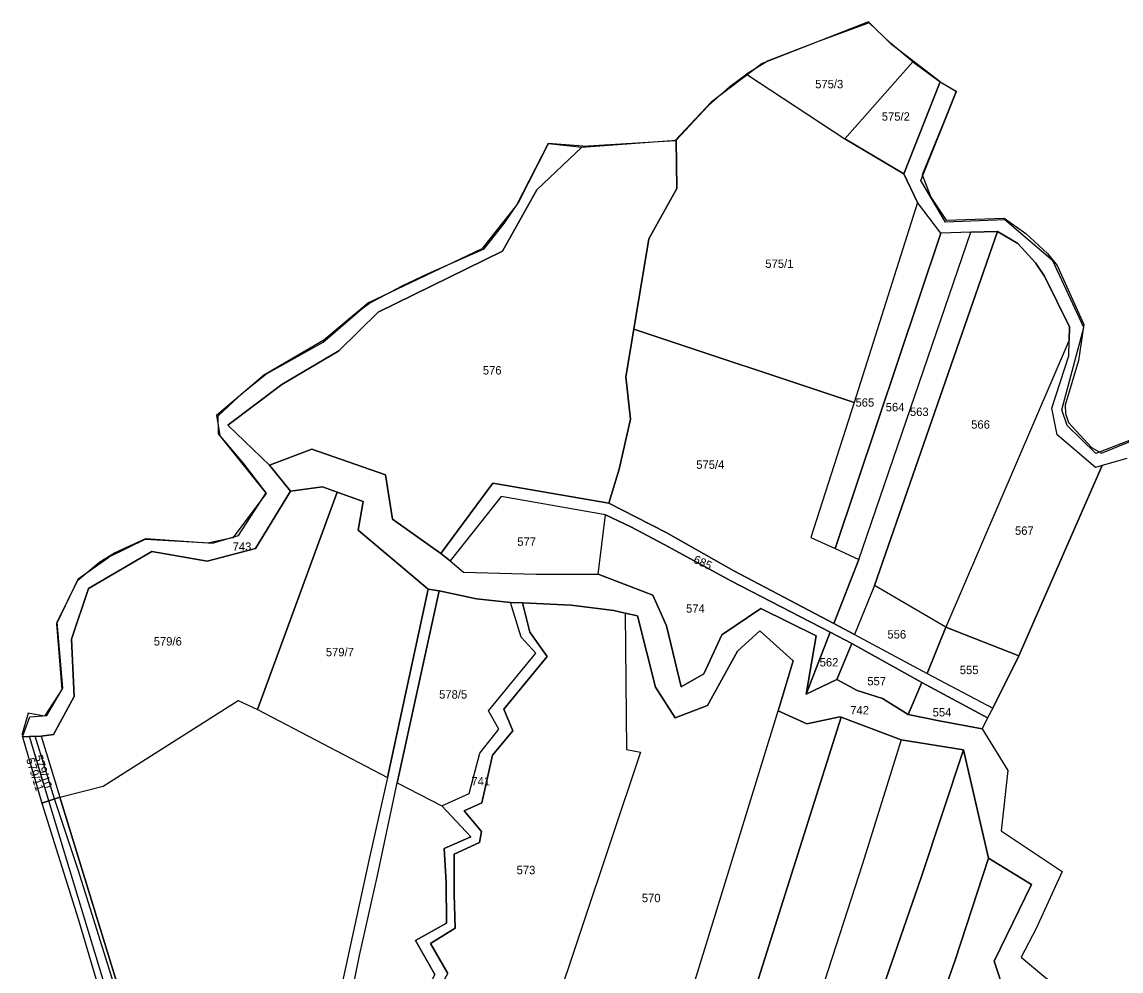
# Model space of a CAD drawing. Extents: x -629983 to -626385, y -1072828 to -1067897.
# Drawn here: x -627758 to -627364.7, y -1068989.9 to -1068650.1 of the extents above; entities that cross this region are included whole.
import ezdxf

# ---------------------------------------------------------------- set-up
doc = ezdxf.new("R2010")
doc.units = 0
for name, color, linetype in [('Katastrální hranice', 7, 'Continuous'), ('Parcela nároku', 7, 'Continuous'), ('Parcelní číslo', 7, 'Continuous'), ('Plocha PÚ', 7, 'Continuous'), ('Převzatý obvod_Opočno', 7, 'Continuous'), ('voda', 7, 'Continuous'), ('Šetřený obvod', 7, 'Continuous')]:
    doc.layers.add(name, color=color, linetype=linetype)

msp = doc.modelspace()

# ---------------------------------------------------------------- linework, layer by layer
at = {"layer": 'Katastrální hranice'}
for p, q in [((-627455.11, -1068650.12), (-627493.17, -1068664.96)), ((-627455.11, -1068650.12), (-627446.8, -1068658.14)), ((-627429.36, -1068671.53), (-627446.8, -1068658.14)), ((-627493.17, -1068664.96), (-627511.39, -1068678.82)), ((-627429.36, -1068671.53), (-627423.57, -1068675.07)), ((-627436.31, -1068706.85), (-627423.57, -1068675.07)), ((-627524.21, -1068692.53), (-627511.39, -1068678.82)), ((-627569.74, -1068693.59), (-627581.07, -1068715.72)), ((-627557.28, -1068694.57), (-627569.74, -1068693.59)), ((-627557.28, -1068694.57), (-627524.21, -1068692.53)), ((-627427.54, -1068721.76), (-627436.31, -1068706.85)), ((-627581.07, -1068715.72), (-627593.27, -1068731.22)), ((-627406.25, -1068720.91), (-627427.54, -1068721.76)), ((-627389.11, -1068735.62), (-627406.25, -1068720.91)), ((-627633.86, -1068750.58), (-627593.27, -1068731.22)), ((-627377.98, -1068759.54), (-627389.11, -1068735.62)), ((-627633.86, -1068750.58), (-627650.01, -1068764.1)), ((-627385.85, -1068788.99), (-627377.98, -1068759.54)), ((-627650.01, -1068764.1), (-627671.8, -1068776.76)), ((-627688.4, -1068790.95), (-627671.8, -1068776.76)), ((-627383.97, -1068794.56), (-627385.85, -1068788.99)), ((-627688.4, -1068790.95), (-627687.18, -1068798.29)), ((-627373.68, -1068804.57), (-627383.97, -1068794.56)), ((-627348.82, -1068794.95), (-627373.68, -1068804.57)), ((-627687.18, -1068798.29), (-627670.68, -1068818.88)), ((-627670.68, -1068818.88), (-627682.56, -1068834.81)), ((-627713.81, -1068835.26), (-627726.87, -1068841.72)), ((-627713.81, -1068835.26), (-627690.98, -1068836.55)), ((-627682.56, -1068834.81), (-627690.98, -1068836.55)), ((-627737.88, -1068849.54), (-627726.87, -1068841.72)), ((-627737.88, -1068849.54), (-627745.69, -1068865.62)), ((-627745.69, -1068865.62), (-627743.7, -1068889.13)), ((-627743.7, -1068889.13), (-627749.97, -1068898.71)), ((-627755.78, -1068897.56), (-627758.01, -1068905.51)), ((-627749.97, -1068898.71), (-627755.78, -1068897.56))]:
    msp.add_line(p, q, dxfattribs=at)
at = {"layer": 'Parcela nároku'}
for points in [[(-627490.96, -1068664.03), (-627498.67, -1068668.81), (-627463.52, -1068692.01), (-627439.18, -1068664.39), (-627447.21, -1068657.71), (-627454.77, -1068650.42), (-627473.7, -1068657.3)], [(-627439.18, -1068664.39), (-627429.39, -1068671.54), (-627442.45, -1068704.48), (-627463.52, -1068692.01)], [(-627498.67, -1068668.81), (-627463.52, -1068692.01), (-627442.45, -1068704.48), (-627437.5, -1068714.76), (-627460.15, -1068786.34), (-627539, -1068760.11), (-627533.65, -1068727.74), (-627523.6, -1068709.74), (-627523.92, -1068692.49), (-627512.49, -1068680.15), (-627504.71, -1068673.23)], [(-627633.69, -1068750.8), (-627621.98, -1068744.53), (-627612.63, -1068740.2), (-627592.6, -1068731.37), (-627585.48, -1068722.31), (-627580.34, -1068714.71), (-627569.56, -1068693.58), (-627557.62, -1068695), (-627573.7, -1068710.26), (-627586, -1068732.13), (-627630.58, -1068754.02), (-627644.57, -1068767.83), (-627665.05, -1068779.97), (-627684.35, -1068794.52), (-627669.38, -1068808.85), (-627661.93, -1068818.14), (-627674.45, -1068838.68), (-627691.7, -1068843.16), (-627711.53, -1068839.7), (-627734.17, -1068852.97), (-627740.31, -1068871.12), (-627739.3, -1068891.66), (-627746.74, -1068905.28), (-627751.2, -1068905.8), (-627755.32, -1068905.92), (-627757.81, -1068906.1), (-627755.18, -1068898.91), (-627749.15, -1068898.42), (-627743.36, -1068888.68), (-627745.46, -1068865.01), (-627738.05, -1068850.02), (-627730.13, -1068843.46), (-627724.95, -1068840.18), (-627713.64, -1068835.08), (-627689.79, -1068836.68), (-627680.5, -1068833.97), (-627670.62, -1068818.72), (-627678.9, -1068807.94), (-627687.66, -1068797.58), (-627687.83, -1068791.16), (-627678.85, -1068782.74), (-627670.79, -1068776.22), (-627650.27, -1068764.77), (-627636.21, -1068752.74)], [(-627573.7, -1068710.26), (-627557.62, -1068695), (-627523.92, -1068692.49), (-627523.6, -1068709.74), (-627533.65, -1068727.74), (-627539, -1068760.11), (-627541.95, -1068777.17), (-627540.2, -1068792.31), (-627544.33, -1068810.18), (-627547.94, -1068822.4), (-627589.48, -1068815.24), (-627608.06, -1068840.38), (-627625.4, -1068828.18), (-627627.89, -1068812.2), (-627654.33, -1068803.12), (-627669.38, -1068808.85), (-627684.35, -1068794.52), (-627665.05, -1068779.97), (-627644.57, -1068767.83), (-627630.58, -1068754.02), (-627586, -1068732.13)], [(-627437.5, -1068714.76), (-627460.15, -1068786.34), (-627475.69, -1068834.7), (-627467, -1068838.66), (-627429.19, -1068725.79)], [(-627458.51, -1068842.52), (-627418.41, -1068725.41), (-627408.85, -1068725.08), (-627452.89, -1068851.86), (-627460.02, -1068869.47), (-627467.46, -1068865.48)], [(-627418.41, -1068725.41), (-627429.19, -1068725.79), (-627467, -1068838.66), (-627458.51, -1068842.52)], [(-627392.06, -1068741.17), (-627383.17, -1068759.27), (-627383.24, -1068764.06), (-627427.39, -1068866.83), (-627452.89, -1068851.86), (-627408.85, -1068725.08), (-627401.61, -1068729.4), (-627395.24, -1068736.35)], [(-627475.69, -1068834.7), (-627467, -1068838.66), (-627458.51, -1068842.52), (-627467.46, -1068865.48), (-627503.28, -1068846.58), (-627527.5, -1068832.85), (-627538.43, -1068827.3), (-627547.94, -1068822.4), (-627544.33, -1068810.18), (-627540.2, -1068792.31), (-627541.95, -1068777.17), (-627539, -1068760.11), (-627460.15, -1068786.34)], [(-627387.58, -1068797.91), (-627389.5, -1068788.39), (-627383.32, -1068769.69), (-627383.24, -1068764.06), (-627427.39, -1068866.83), (-627401.24, -1068877.1), (-627371.38, -1068808.97), (-627373.8, -1068809.67)], [(-627674.45, -1068838.68), (-627691.7, -1068843.16), (-627711.53, -1068839.7), (-627734.17, -1068852.97), (-627740.31, -1068871.12), (-627739.3, -1068891.66), (-627746.74, -1068905.28), (-627751.2, -1068905.8), (-627744.49, -1068927.66), (-627728.98, -1068923.71), (-627680.68, -1068893.1), (-627673.72, -1068896.3), (-627645.24, -1068818.48), (-627650.51, -1068816.61), (-627661.93, -1068818.14)], [(-627503.28, -1068846.58), (-627467.46, -1068865.48), (-627460.02, -1068869.47), (-627434.12, -1068883.37), (-627410.57, -1068895.79), (-627412.43, -1068899.29), (-627435.94, -1068886.61), (-627461.05, -1068872.59), (-627468.79, -1068868.6), (-627504.04, -1068850.31), (-627528.21, -1068837.16), (-627540.16, -1068830.9), (-627549.22, -1068826.63), (-627586.5, -1068820.05), (-627604.77, -1068843.1), (-627608.06, -1068840.38), (-627589.48, -1068815.24), (-627547.94, -1068822.4), (-627538.43, -1068827.3), (-627527.5, -1068832.85)], [(-627612.67, -1068853.16), (-627637.71, -1068832.1), (-627635.93, -1068821.79), (-627645.24, -1068818.48), (-627673.72, -1068896.3), (-627627.23, -1068920.63)], [(-627549.22, -1068826.63), (-627586.5, -1068820.05), (-627604.77, -1068843.1), (-627599.99, -1068847.08), (-627574.02, -1068847.86), (-627551.82, -1068847.76)], [(-627551.82, -1068847.76), (-627549.22, -1068826.63), (-627540.16, -1068830.9), (-627528.21, -1068837.16), (-627504.04, -1068850.31), (-627468.79, -1068868.6), (-627477.32, -1068890.81), (-627473.76, -1068869.93), (-627493.55, -1068860.11), (-627507.58, -1068869.57), (-627514.01, -1068883.46), (-627522.15, -1068888.21), (-627527.33, -1068866.35), (-627532.21, -1068855.29)], [(-627452.89, -1068851.86), (-627460.02, -1068869.47), (-627434.12, -1068883.37), (-627427.39, -1068866.83)], [(-627663.03, -1069095.94), (-627666.3, -1069131.69), (-627668.24, -1069161.01), (-627665.38, -1069164.4), (-627662.79, -1069131.38), (-627658.99, -1069092.21), (-627637.25, -1068984.36), (-627630.77, -1068955.68), (-627623.72, -1068922.54), (-627608.67, -1068853.79), (-627612.67, -1068853.16), (-627627.23, -1068920.63), (-627633.84, -1068950.3), (-627645.34, -1069002.98), (-627653.33, -1069042.58), (-627660.07, -1069078.95)], [(-627595.36, -1068856.65), (-627608.67, -1068853.79), (-627623.72, -1068922.54), (-627607.72, -1068930.75), (-627597.94, -1068926.36), (-627594.14, -1068911.85), (-627587.36, -1068903.27), (-627591.09, -1068896.7), (-627574.14, -1068876.14), (-627579.41, -1068870.37), (-627583.13, -1068857.99)], [(-627541.67, -1068910.56), (-627536.66, -1068911.49), (-627578.96, -1069038.13), (-627619.33, -1069015.15), (-627605.58, -1068990.76), (-627611.83, -1068980.04), (-627603.02, -1068974.61), (-627603.36, -1068962.42), (-627603.37, -1068948.03), (-627594.26, -1068943.85), (-627593.58, -1068939.95), (-627599.72, -1068932.52), (-627593.42, -1068929.74), (-627589.61, -1068912.68), (-627582.29, -1068903.91), (-627585.58, -1068896.11), (-627570.08, -1068877.27), (-627576.3, -1068868.62), (-627578.92, -1068858.11), (-627561.45, -1068858.96), (-627546.19, -1068860.81), (-627542.18, -1068861.77)], [(-627512.64, -1068894.88), (-627524.24, -1068899.27), (-627531.23, -1068888.31), (-627537.68, -1068862.77), (-627542.18, -1068861.77), (-627541.67, -1068910.56), (-627536.66, -1068911.49), (-627578.96, -1069038.13), (-627576.57, -1069039.46), (-627535.1, -1069051.69), (-627487.33, -1068896.72), (-627481.96, -1068878.87), (-627493.96, -1068868.07), (-627501.98, -1068875.39)], [(-627477.32, -1068890.81), (-627468.79, -1068868.6), (-627461.05, -1068872.59), (-627466.34, -1068885.58)], [(-627401.24, -1068877.1), (-627427.39, -1068866.83), (-627434.12, -1068883.37), (-627410.57, -1068895.79)], [(-627461.05, -1068872.59), (-627435.94, -1068886.61), (-627440.85, -1068898.05), (-627450.01, -1068892.29), (-627459.16, -1068889.46), (-627466.34, -1068885.58)], [(-627440.85, -1068898.05), (-627435.94, -1068886.61), (-627412.43, -1068899.29), (-627414.33, -1068903.23), (-627429.77, -1068900.38)], [(-627680.68, -1068893.1), (-627673.72, -1068896.3), (-627627.23, -1068920.63), (-627633.84, -1068950.3), (-627645.34, -1069002.98), (-627653.33, -1069042.58), (-627660.07, -1069078.95), (-627663.03, -1069095.94), (-627666.3, -1069131.69), (-627668.24, -1069161.01), (-627672.57, -1069156.47), (-627684.37, -1069135.35), (-627710.62, -1069037.96), (-627744.49, -1068927.66), (-627728.98, -1068923.71)], [(-627569.68, -1069170.14), (-627535.1, -1069051.69), (-627487.33, -1068896.72), (-627477.1, -1068901.39), (-627465.34, -1068898.88), (-627464.83, -1068899.07), (-627506.25, -1069029.91), (-627556.61, -1069184.03), (-627566.39, -1069211.09), (-627580.43, -1069202.71)], [(-627556.61, -1069184.03), (-627506.25, -1069029.91), (-627464.83, -1068899.07), (-627443.39, -1068907.08), (-627457.17, -1068951.58), (-627510.15, -1069115.2), (-627546.54, -1069223.62), (-627566.39, -1069211.09)], [(-627748.35, -1068928.94), (-627755.32, -1068905.92), (-627757.81, -1068906.1), (-627750.88, -1068929.78)], [(-627751.2, -1068905.8), (-627744.49, -1068927.66), (-627748.35, -1068928.94), (-627755.32, -1068905.92)], [(-627510.15, -1069115.2), (-627546.54, -1069223.62), (-627539.83, -1069227.42), (-627530.47, -1069232.83), (-627492.9, -1069120.08), (-627436.21, -1068956.4), (-627421.11, -1068910.74), (-627443.39, -1068907.08), (-627457.17, -1068951.58)], [(-627412.16, -1068949.45), (-627421.11, -1068910.74), (-627436.21, -1068956.4), (-627492.9, -1069120.08), (-627472.93, -1069124.75), (-627424.1, -1068986.06)], [(-627662.79, -1069131.38), (-627658.99, -1069092.21), (-627637.25, -1068984.36), (-627630.77, -1068955.68), (-627623.72, -1068922.54), (-627607.72, -1068930.75), (-627597.33, -1068941.88), (-627606.91, -1068946.03), (-627606.23, -1068958.26), (-627606.09, -1068972.77), (-627617.12, -1068979.03), (-627610.22, -1068991.12), (-627624.74, -1069017.84), (-627624, -1069034.55), (-627633.33, -1069045.36), (-627636.7, -1069076.5), (-627642.58, -1069085.74), (-627642.61, -1069102.64), (-627650.94, -1069114.12), (-627649.85, -1069130.94), (-627649.97, -1069139.58), (-627657.58, -1069143.79), (-627661.43, -1069169.08), (-627665.38, -1069164.4)], [(-627672.57, -1069156.47), (-627668.24, -1069161.01), (-627669.41, -1069170.58), (-627679.98, -1069159.96), (-627689.67, -1069139.02), (-627711.97, -1069050.84), (-627725.33, -1069004.9), (-627748.35, -1068928.94), (-627744.49, -1068927.66), (-627710.62, -1069037.96), (-627684.37, -1069135.35)], [(-627669.41, -1069170.58), (-627679.98, -1069159.96), (-627689.67, -1069139.02), (-627711.97, -1069050.84), (-627725.33, -1069004.9), (-627748.35, -1068928.94), (-627750.88, -1068929.78), (-627737.89, -1068971.16), (-627728.35, -1069003.46), (-627721.01, -1069026.12), (-627716.42, -1069043.96), (-627710.61, -1069071.05), (-627703.7, -1069107.81), (-627700.64, -1069124.1), (-627694.93, -1069153.57), (-627693.1, -1069165.44), (-627691.51, -1069182.4), (-627651.18, -1069188.9), (-627657.71, -1069182.34), (-627664.84, -1069178.41), (-627669.64, -1069172.47)], [(-627424.1, -1068986.06), (-627472.93, -1069124.75), (-627451.96, -1069129.61), (-627406.09, -1068998.31), (-627410.09, -1068986.34), (-627396.68, -1068958.95), (-627412.16, -1068949.45)]]:
    msp.add_lwpolyline(points, close=True, dxfattribs=at)
for points in [[(-627362.58, -1068806.41), (-627371.38, -1068808.97), (-627373.8, -1068809.67), (-627387.58, -1068797.91), (-627389.5, -1068788.39), (-627383.32, -1068769.69), (-627383.24, -1068764.06), (-627383.17, -1068759.27), (-627392.06, -1068741.17), (-627395.24, -1068736.35), (-627401.61, -1068729.4), (-627408.85, -1068725.08), (-627418.41, -1068725.41), (-627429.19, -1068725.79), (-627437.5, -1068714.76), (-627442.45, -1068704.48), (-627429.39, -1068671.54), (-627423.63, -1068674.95), (-627428.19, -1068686.26), (-627435.86, -1068704.86), (-627432.75, -1068712.79), (-627427.22, -1068721.05), (-627406.51, -1068720.41), (-627398.73, -1068725.91), (-627390.95, -1068733.02), (-627387.56, -1068737.3), (-627378.02, -1068758.4), (-627379.94, -1068771.37), (-627384.72, -1068787.32), (-627384.57, -1068790.33), (-627383.54, -1068793.55), (-627375.3, -1068802.42), (-627371.69, -1068804.54), (-627347.69, -1068794.68)], [(-627406.09, -1068998.31), (-627410.09, -1068986.34), (-627396.68, -1068958.95), (-627412.16, -1068949.45), (-627421.11, -1068910.74), (-627443.39, -1068907.08), (-627464.83, -1068899.07), (-627465.34, -1068898.88), (-627477.1, -1068901.39), (-627487.33, -1068896.72), (-627481.96, -1068878.87), (-627493.96, -1068868.07), (-627501.98, -1068875.39), (-627512.64, -1068894.88), (-627524.24, -1068899.27), (-627531.23, -1068888.31), (-627537.68, -1068862.77), (-627542.18, -1068861.77), (-627546.19, -1068860.81), (-627561.45, -1068858.96), (-627578.92, -1068858.11), (-627583.13, -1068857.99), (-627595.36, -1068856.65), (-627608.67, -1068853.79), (-627612.67, -1068853.16), (-627637.71, -1068832.1), (-627635.93, -1068821.79), (-627645.24, -1068818.48), (-627650.51, -1068816.61), (-627661.93, -1068818.14), (-627669.38, -1068808.85), (-627654.33, -1068803.12), (-627627.89, -1068812.2), (-627625.4, -1068828.18), (-627608.06, -1068840.38), (-627604.77, -1068843.1), (-627599.99, -1068847.08), (-627574.02, -1068847.86), (-627551.82, -1068847.76), (-627532.21, -1068855.29), (-627527.33, -1068866.35), (-627522.15, -1068888.21), (-627514.01, -1068883.46), (-627507.58, -1068869.57), (-627493.55, -1068860.11), (-627473.76, -1068869.93), (-627477.32, -1068890.81), (-627466.34, -1068885.58), (-627459.16, -1068889.46), (-627450.01, -1068892.29), (-627440.85, -1068898.05), (-627429.77, -1068900.38), (-627414.33, -1068903.23), (-627405.19, -1068918.16), (-627407.52, -1068939.7), (-627385.79, -1068954.28), (-627395.08, -1068974.68), (-627400.42, -1068984.9), (-627388.67, -1068994.83)], [(-627362.58, -1068806.41), (-627371.38, -1068808.97), (-627401.24, -1068877.1), (-627410.57, -1068895.79), (-627412.43, -1068899.29), (-627414.33, -1068903.23), (-627405.19, -1068918.16), (-627407.52, -1068939.7), (-627385.79, -1068954.28), (-627395.08, -1068974.68), (-627400.42, -1068984.9), (-627388.67, -1068994.83)], [(-627610.22, -1068991.12), (-627617.12, -1068979.03), (-627606.09, -1068972.77), (-627606.23, -1068958.26), (-627606.91, -1068946.03), (-627597.33, -1068941.88), (-627607.72, -1068930.75), (-627597.94, -1068926.36), (-627594.14, -1068911.85), (-627587.36, -1068903.27), (-627591.09, -1068896.7), (-627574.14, -1068876.14), (-627579.41, -1068870.37), (-627583.13, -1068857.99), (-627578.92, -1068858.11), (-627576.3, -1068868.62), (-627570.08, -1068877.27), (-627585.58, -1068896.11), (-627582.29, -1068903.91), (-627589.61, -1068912.68), (-627593.42, -1068929.74), (-627599.72, -1068932.52), (-627593.58, -1068939.95), (-627594.26, -1068943.85), (-627603.37, -1068948.03), (-627603.36, -1068962.42), (-627603.02, -1068974.61), (-627611.83, -1068980.04), (-627605.58, -1068990.76)]]:
    msp.add_lwpolyline(points, dxfattribs=at)
at = {"layer": 'Plocha PÚ'}
msp.add_line((-627608.67, -1068853.79), (-627612.67, -1068853.16), dxfattribs=at)
for points in [[(-627612.67, -1068853.16), (-627637.71, -1068832.1), (-627635.93, -1068821.79), (-627645.24, -1068818.48), (-627650.51, -1068816.61), (-627661.93, -1068818.14), (-627674.45, -1068838.68), (-627691.7, -1068843.16), (-627711.53, -1068839.7), (-627734.17, -1068852.97), (-627740.31, -1068871.12), (-627739.3, -1068891.66), (-627746.74, -1068905.28), (-627751.2, -1068905.8), (-627755.32, -1068905.92), (-627757.81, -1068906.1), (-627750.88, -1068929.78), (-627737.89, -1068971.16), (-627728.35, -1069003.46)], [(-627406.09, -1068998.31), (-627410.09, -1068986.34), (-627396.68, -1068958.95), (-627412.16, -1068949.45), (-627421.11, -1068910.74), (-627443.39, -1068907.08), (-627464.83, -1068899.07), (-627465.34, -1068898.88), (-627477.1, -1068901.39), (-627487.33, -1068896.72), (-627481.96, -1068878.87), (-627493.96, -1068868.07), (-627501.98, -1068875.39), (-627512.64, -1068894.88), (-627524.24, -1068899.27), (-627531.23, -1068888.31), (-627537.68, -1068862.77), (-627542.18, -1068861.77), (-627546.19, -1068860.81), (-627561.45, -1068858.96), (-627578.92, -1068858.11), (-627583.13, -1068857.99), (-627595.36, -1068856.65), (-627608.67, -1068853.79)]]:
    msp.add_lwpolyline(points, dxfattribs=at)
at = {"layer": 'Převzatý obvod_Opočno'}
msp.add_lwpolyline([(-627757.81, -1068906.1), (-627750.88, -1068929.78), (-627737.89, -1068971.16), (-627728.35, -1069003.46)], dxfattribs=at)
at = {"layer": 'voda'}
msp.add_lwpolyline([(-627608.69, -1069228.58), (-627636.98, -1069203.42), (-627659.65, -1069186.99), (-627674.7, -1069165.27), (-627684.43, -1069143.51), (-627696.42, -1069101.03), (-627709.87, -1069053.38), (-627717.07, -1069020.38), (-627737.92, -1068953.69), (-627746.42, -1068928.3), (-627753.26, -1068905.86)], dxfattribs=at)
at = {"layer": 'Šetřený obvod'}
for p, q in [((-627661.93, -1068818.14), (-627650.51, -1068816.61)), ((-627650.51, -1068816.61), (-627645.24, -1068818.48)), ((-627674.45, -1068838.68), (-627661.93, -1068818.14)), ((-627645.24, -1068818.48), (-627635.93, -1068821.79)), ((-627635.93, -1068821.79), (-627637.71, -1068832.1)), ((-627637.71, -1068832.1), (-627612.67, -1068853.16)), ((-627734.17, -1068852.97), (-627711.53, -1068839.7)), ((-627711.53, -1068839.7), (-627691.7, -1068843.16)), ((-627691.7, -1068843.16), (-627674.45, -1068838.68)), ((-627740.31, -1068871.12), (-627734.17, -1068852.97)), ((-627612.67, -1068853.16), (-627608.67, -1068853.79)), ((-627608.67, -1068853.79), (-627595.36, -1068856.65)), ((-627595.36, -1068856.65), (-627583.13, -1068857.99)), ((-627583.13, -1068857.99), (-627578.92, -1068858.11)), ((-627578.92, -1068858.11), (-627561.45, -1068858.96)), ((-627561.45, -1068858.96), (-627546.19, -1068860.81)), ((-627546.19, -1068860.81), (-627542.18, -1068861.77)), ((-627542.18, -1068861.77), (-627537.68, -1068862.77)), ((-627537.68, -1068862.77), (-627531.23, -1068888.31)), ((-627501.98, -1068875.39), (-627493.96, -1068868.07)), ((-627493.96, -1068868.07), (-627481.96, -1068878.87)), ((-627739.3, -1068891.66), (-627740.31, -1068871.12)), ((-627512.64, -1068894.88), (-627501.98, -1068875.39)), ((-627481.96, -1068878.87), (-627487.33, -1068896.72)), ((-627531.23, -1068888.31), (-627524.24, -1068899.27)), ((-627746.74, -1068905.28), (-627739.3, -1068891.66)), ((-627524.24, -1068899.27), (-627512.64, -1068894.88)), ((-627487.33, -1068896.72), (-627477.1, -1068901.39)), ((-627477.1, -1068901.39), (-627465.34, -1068898.88)), ((-627465.34, -1068898.88), (-627464.83, -1068899.07)), ((-627464.83, -1068899.07), (-627443.39, -1068907.08)), ((-627757.81, -1068906.1), (-627755.32, -1068905.92)), ((-627755.32, -1068905.92), (-627751.2, -1068905.8)), ((-627751.2, -1068905.8), (-627746.74, -1068905.28)), ((-627443.39, -1068907.08), (-627421.11, -1068910.74)), ((-627421.11, -1068910.74), (-627412.16, -1068949.45)), ((-627412.16, -1068949.45), (-627396.68, -1068958.95)), ((-627396.68, -1068958.95), (-627410.09, -1068986.34)), ((-627410.09, -1068986.34), (-627406.09, -1068998.31))]:
    msp.add_line(p, q, dxfattribs=at)

# ---------------------------------------------------------------- texts
at = {"layer": 'Parcelní číslo'}
for s, p in [('575/3', (-627474.14, -1068673.86)), ('575/2', (-627450.3, -1068685.46)), ('575/1', (-627491.98, -1068738.18)), ('576', (-627593.08, -1068776.34)), ('565', (-627459.71, -1068787.85)), ('564', (-627448.9, -1068789.51)), ('563', (-627440.23, -1068791.18)), ('566', (-627418.31, -1068795.72)), ('575/4', (-627516.7, -1068810.1)), ('567', (-627402.63, -1068833.73)), ('743', (-627682.62, -1068839.45)), ('577', (-627580.74, -1068837.66)), ('574', (-627520.35, -1068861.6)), ('556', (-627448.28, -1068870.87)), ('579/6', (-627710.85, -1068873.36)), ('579/7', (-627649.27, -1068877.22)), ('562', (-627472.53, -1068880.86)), ('555', (-627422.4, -1068883.61)), ('557', (-627455.47, -1068887.63)), ('578/5', (-627608.73, -1068892.37)), ('742', (-627461.58, -1068898.03)), ('554', (-627432.1, -1068898.77)), ('741', (-627597.18, -1068923.47)), ('573', (-627580.99, -1068955.24)), ('570', (-627536.17, -1068965.26))]:
    msp.add_text(s, height=3, dxfattribs=at).set_placement(p)
for s, rotation, p in [('685', 335.5284, (-627518.01, -1068843.6)), ('579/11', 287.2395, (-627756.59, -1068914.1)), ('579/10', 286.9847, (-627753.62, -1068913.03))]:
    msp.add_text(s, height=3, rotation=rotation, dxfattribs=at).set_placement(p)

doc.saveas('drawing.dxf')
